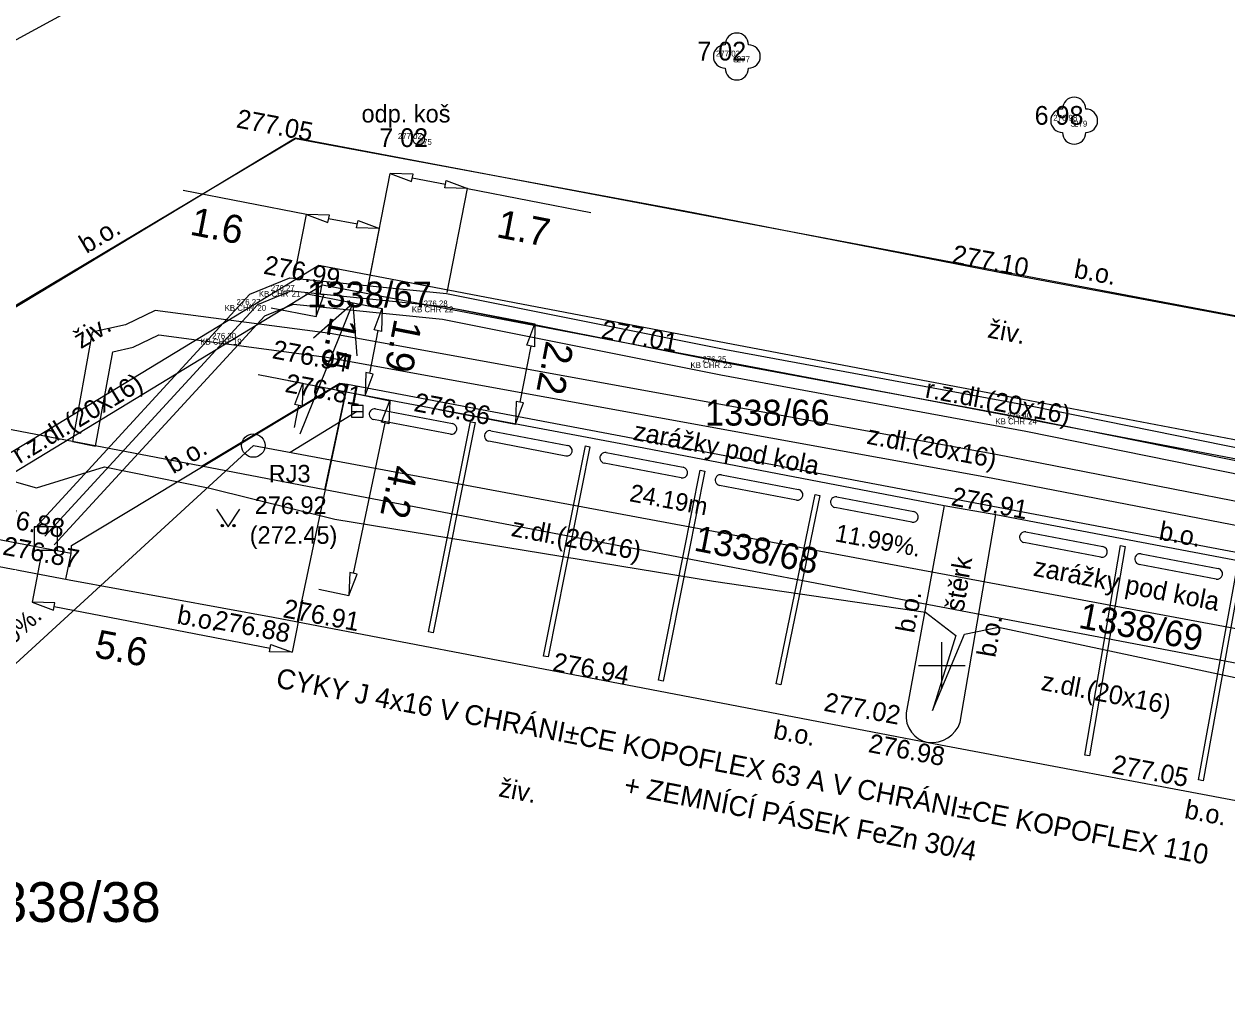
# Model space of a CAD drawing. Extents: x -601602 to -600882, y -1162594 to -1161950.
# Drawn here: x -601269.56 to -601243.92, y -1162082.3 to -1162061.32 of the extents above; entities that cross this region are included whole.
import ezdxf

# ---------------------------------------------------------------- set-up
doc = ezdxf.new("R2010")
doc.units = 0
for name, color, linetype in [('BODY', 7, 'Continuous'), ('BODY_CISLA', 7, 'Continuous'), ('BODY_KODY', 7, 'Continuous'), ('BODY_VYSKY_CELE', 7, 'Continuous'), ('G_TEXTY', 7, 'Continuous'), ('G_ZELEN', 7, 'Continuous'), ('G_ZNACKY', 7, 'Continuous'), ('H_KOTY_VYSKOVE', 7, 'Continuous'), ('H_VYSKY_PREVZATE', 7, 'Continuous'), ('IS_CHRÁNIČKY', 7, 'Continuous'), ('IS_KAN_JEDNOTNA', 7, 'Continuous'), ('IS_ODVODNĚNÍ', 7, 'Continuous'), ('IS_VO_PRELOZKA', 7, 'Continuous'), ('KN_Hranice parcel', 7, 'Continuous'), ('KN_Parcelní čísla', 7, 'Continuous'), ('KN_Pop  PČ popisy', 7, 'Continuous'), ('KN_Věcná břemena k části', 7, 'Continuous'), ('Vrstva 14', 7, 'Continuous'), ('Vrstva 23', 7, 'Continuous'), ('Vrstva 25', 7, 'Continuous'), ('VRSTVA 40', 7, 'Continuous'), ('Vrstva 49', 7, 'Continuous'), ('VRSTVA 5', 7, 'Continuous'), ('Vrstva 7', 7, 'Continuous'), ('X_SOUR_KRIZKY_SEVER', 7, 'Continuous')]:
    doc.layers.add(name, color=color, linetype=linetype)

# ---------------------------------------------------------------- blocks, each defined once
blk = doc.blocks.new('POINT_DISPLAY')
blk.add_line((0, 0), (0, 0))
blk = doc.blocks.new('1029_88')
at = {"layer": 'KN_Pop  PČ popisy'}
for p, q in [((0, 0), (1.124, 2.782)), ((1.124, 2.782), (0.285, 2.042)), ((1.124, 2.782), (1.213, 1.666))]:
    blk.add_line(p, q, dxfattribs=at)

msp = doc.modelspace()

# ---------------------------------------------------------------- linework, layer by layer
at = {"layer": 'G_ZELEN'}
for centre in [(-601254.37, -1162062.01), (-601247.18, -1162063.38)]:
    msp.add_circle(centre, 0.00025, dxfattribs=at)
for centre, start, end in [((-601254.37, -1162061.76), 0, 180), ((-601254.62, -1162062.01), 90, 270), ((-601254.12, -1162062.01), 270, 90), ((-601254.37, -1162062.26), 180, 360), ((-601247.18, -1162063.13), 0, 180), ((-601247.43, -1162063.38), 90, 270), ((-601246.93, -1162063.38), 270, 90), ((-601247.18, -1162063.63), 180, 360)]:
    msp.add_arc(centre, 0.25, start, end, dxfattribs=at)
at = {"layer": 'G_ZNACKY'}
for centre, radius in [((-601261.15, -1162063.77), 0.125), ((-601261.15, -1162063.77), 0.00025), ((-601264.676, -1162070.309), 0.25)]:
    msp.add_circle(centre, radius, dxfattribs=at)
at = {"layer": 'IS_CHRÁNIČKY'}
for points in [[(-601269.322, -1162072.054), (-601264.751, -1162067.079), (-601263.901, -1162066.729), (-601260.559, -1162067.068), (-601254.608, -1162068.26), (-601248.108, -1162069.46), (-601239.768, -1162071.15), (-601235.321, -1162071.969), (-601188.223, -1162080.219), (-601187.191, -1162077.25), (-601187.253, -1162076.744)], [(-601268.918, -1162072.426), (-601264.429, -1162067.541), (-601263.819, -1162067.291), (-601260.641, -1162067.612), (-601254.712, -1162068.8), (-601248.212, -1162070), (-601239.872, -1162071.69), (-601235.419, -1162072.511), (-601187.857, -1162080.841), (-601186.629, -1162077.31), (-601186.707, -1162076.676)]]:
    msp.add_lwpolyline(points, dxfattribs=at)
at = {"layer": 'IS_KAN_JEDNOTNA'}
msp.add_lwpolyline([(-601284.233, -1162104.983), (-601281.181, -1162099.025), (-601277.302, -1162081.896), (-601264.676, -1162070.309), (-601240.903, -1162074.739), (-601224.554, -1162077.728), (-601180.153, -1162087.436), (-601164.522, -1162091.613), (-601134.295, -1162101.261)], dxfattribs=at)
at = {"layer": 'IS_ODVODNĚNÍ'}
msp.add_line((-601262.46, -1162069.58), (-601263.89, -1162070.456), dxfattribs=at)
at = {"layer": 'IS_VO_PRELOZKA'}
msp.add_lwpolyline([(-601277.25, -1162070.85), (-601276.92, -1162070.27), (-601276.21, -1162070.04), (-601270.43, -1162070.89), (-601269.3, -1162071.21), (-601267.85, -1162070.76), (-601267.85, -1162070.76), (-601265.6, -1162071.22), (-601262.94, -1162071.88), (-601254.87, -1162073.2), (-601250.35, -1162073.86), (-601249.7, -1162074.36), (-601250.2, -1162075.96), (-601249.52, -1162074.33), (-601248.79, -1162074.18), (-601240.94, -1162075.85), (-601238.61, -1162076.29), (-601226.51, -1162078.06), (-601223.39, -1162080.54), (-601226.51, -1162078.06), (-601238.61, -1162076.29), (-601238.61, -1162076.29)], dxfattribs=at)
at = {"layer": 'KN_Hranice parcel'}
for p, q in [((-601263.15, -1162071.25), (-601262.67, -1162069)), ((-601262.67, -1162069), (-601240.88, -1162073.12)), ((-601265.78, -1162070.75), (-601273.06, -1162069.36)), ((-601263.15, -1162071.25), (-601265.78, -1162070.75))]:
    msp.add_line(p, q, dxfattribs=at)
for points in [[(-601238.38, -1162068.56), (-601263.78, -1162063.75), (-601273.06, -1162069.36)], [(-601265.78, -1162070.75), (-601262.83, -1162068.98), (-601262.67, -1162069)], [(-601241.2, -1162074.96), (-601241.86, -1162075.07), (-601242.73, -1162075.09), (-601243.52, -1162074.99), (-601263.15, -1162071.25)]]:
    msp.add_lwpolyline(points, dxfattribs=at)
at = {"layer": 'KN_Věcná břemena k části'}
msp.add_lwpolyline([(-601239.85, -1162072.76), (-601239.69, -1162072.29), (-601248.85, -1162070.5), (-601263.04, -1162067.92), (-601266.77, -1162067.43), (-601267.4, -1162067.73), (-601268.11, -1162067.89), (-601268.53, -1162070.22), (-601268.04, -1162070.32), (-601267.67, -1162068.31), (-601267.24, -1162068.21), (-601266.69, -1162067.95), (-601263.12, -1162068.42), (-601248.95, -1162071)], close=True, dxfattribs=at)
at = {"layer": 'Vrstva 14'}
for p, q in [((-601265.463, -1162071.667), (-601265.213, -1162072.042)), ((-601265.213, -1162072.042), (-601264.963, -1162071.667))]:
    msp.add_line(p, q, dxfattribs=at)
for points in [[(-601265.338, -1162072.042), (-601265.363, -1162072.017), (-601265.338, -1162071.992)], [(-601265.338, -1162072.042), (-601265.338, -1162071.992), (-601265.313, -1162072.017)], [(-601265.088, -1162072.042), (-601265.113, -1162072.017), (-601265.088, -1162071.992)], [(-601265.088, -1162072.042), (-601265.088, -1162071.992), (-601265.063, -1162072.017)]]:
    msp.add_lwpolyline(points, close=True, dxfattribs=at)
for centre in [(-601265.338, -1162072.017), (-601265.088, -1162072.017)]:
    msp.add_circle(centre, 0.025, dxfattribs=at)
at = {"layer": 'Vrstva 23'}
for p, q in [((-601268.85, -1162072.04), (-601269.35, -1162072.04)), ((-601269.35, -1162072.04), (-601269.35, -1162072.54)), ((-601268.85, -1162072.54), (-601268.85, -1162072.04)), ((-601269.35, -1162072.54), (-601268.85, -1162072.54))]:
    msp.add_line(p, q, dxfattribs=at)
at = {"layer": 'Vrstva 25'}
for p, q in [((-601262.335, -1162069.455), (-601262.585, -1162069.455)), ((-601262.585, -1162069.455), (-601262.585, -1162069.706)), ((-601262.585, -1162069.58), (-601262.335, -1162069.58)), ((-601262.335, -1162069.706), (-601262.335, -1162069.455)), ((-601262.585, -1162069.706), (-601262.335, -1162069.706)), ((-601262.585, -1162069.706), (-601262.585, -1162069.706))]:
    msp.add_line(p, q, dxfattribs=at)
at = {"layer": 'VRSTVA 40'}
for p, q in [((-601262.191, -1162066.724), (-601261.759, -1162064.507)), ((-601261.287, -1162064.598), (-601260.582, -1162064.736)), ((-601263.542, -1162065.378), (-601266.172, -1162064.865)), ((-601260.543, -1162067.046), (-601260.111, -1162064.828)), ((-601260.111, -1162064.828), (-601257.48, -1162065.34)), ((-601263.803, -1162066.716), (-601263.542, -1162065.378)), ((-601262.458, -1162065.589), (-601263.071, -1162065.469)), ((-601262.248, -1162067.018), (-601261.987, -1162065.68)), ((-601263.248, -1162067.083), (-601263.156, -1162066.612)), ((-601263.566, -1162067.067), (-601261.932, -1162067.386)), ((-601264.296, -1162067.368), (-601263.34, -1162067.554)), ((-601260.305, -1162067.397), (-601258.673, -1162067.714)), ((-601262.024, -1162067.857), (-601262.202, -1162068.768)), ((-601258.764, -1162068.185), (-601258.996, -1162069.381)), ((-601264.574, -1162068.792), (-601263.619, -1162068.979)), ((-601263.927, -1162068.921), (-601262.293, -1162069.239)), ((-601262.406, -1162069.222), (-601261.769, -1162069.356)), ((-601263.711, -1162069.45), (-601263.803, -1162069.921)), ((-601260.72, -1162069.536), (-601259.088, -1162069.852)), ((-601262.544, -1162073.035), (-601261.868, -1162069.826)), ((-601269.177, -1162072.535), (-601269.392, -1162073.65)), ((-601263.28, -1162073.37), (-601262.643, -1162073.504)), ((-601268.92, -1162073.741), (-601264.317, -1162074.627)), ((-601263.631, -1162073.603), (-601263.845, -1162074.718))]:
    msp.add_line(p, q, dxfattribs=at)
for points in [[(-601261.303, -1162064.677), (-601261.272, -1162064.52), (-601261.759, -1162064.507)], [(-601260.597, -1162064.814), (-601260.566, -1162064.657), (-601260.111, -1162064.828)], [(-601263.086, -1162065.548), (-601263.056, -1162065.391), (-601263.542, -1162065.378)], [(-601262.474, -1162065.667), (-601262.443, -1162065.51), (-601261.987, -1162065.68)], [(-601263.17, -1162067.099), (-601263.327, -1162067.068), (-601263.34, -1162067.554)], [(-601261.946, -1162067.872), (-601262.103, -1162067.841), (-601261.932, -1162067.386)], [(-601258.686, -1162068.2), (-601258.843, -1162068.17), (-601258.673, -1162067.714)], [(-601262.123, -1162068.783), (-601262.28, -1162068.753), (-601262.293, -1162069.239)], [(-601263.633, -1162069.465), (-601263.79, -1162069.435), (-601263.619, -1162068.979)], [(-601261.79, -1162069.842), (-601261.946, -1162069.809), (-601261.769, -1162069.356)], [(-601258.918, -1162069.396), (-601259.075, -1162069.366), (-601259.088, -1162069.852)], [(-601262.466, -1162073.051), (-601262.622, -1162073.018), (-601262.643, -1162073.504)], [(-601268.935, -1162073.819), (-601268.905, -1162073.662), (-601269.392, -1162073.65)], [(-601264.332, -1162074.706), (-601264.302, -1162074.549), (-601263.845, -1162074.718)]]:
    msp.add_lwpolyline(points, close=True, dxfattribs=at)
at = {"layer": 'VRSTVA 5'}
for p, q in [((-601263.86, -1162067.01), (-601264.59, -1162067.31)), ((-601263.86, -1162067.01), (-601260.6, -1162067.34)), ((-601264.59, -1162067.31), (-601269.12, -1162072.24)), ((-601260.6, -1162067.34), (-601254.66, -1162068.53)), ((-601254.66, -1162068.53), (-601248.16, -1162069.73)), ((-601248.16, -1162069.73), (-601239.82, -1162071.42))]:
    msp.add_line(p, q, dxfattribs=at)
at = {"layer": 'Vrstva 7'}
for p, q in [((-601273.54, -1162063.74), (-601268.18, -1162060.8)), ((-601273.03, -1162069.28), (-601263.78, -1162063.76)), ((-601263.78, -1162063.76), (-601255.48, -1162065.3)), ((-601255.48, -1162065.3), (-601248.56, -1162066.65)), ((-601270.7, -1162070.97), (-601263.28, -1162066.46)), ((-601263.28, -1162066.46), (-601256.02, -1162067.85)), ((-601248.56, -1162066.65), (-601239.96, -1162068.26)), ((-601270.34, -1162071.22), (-601263.2, -1162066.88)), ((-601263.2, -1162066.88), (-601256.09, -1162068.24)), ((-601256.02, -1162067.85), (-601249.02, -1162069.18)), ((-601256.09, -1162068.24), (-601249.09, -1162069.57)), ((-601268.55, -1162072.44), (-601262.83, -1162068.99)), ((-601262.83, -1162068.99), (-601262.66, -1162069.01)), ((-601262.66, -1162069.01), (-601262.7, -1162069.16)), ((-601263.734, -1162074.069), (-601262.7, -1162069.16)), ((-601262.7, -1162069.16), (-601256.35, -1162070.36)), ((-601249.02, -1162069.18), (-601240.39, -1162070.82)), ((-601262.07, -1162069.527), (-601260.43, -1162069.841)), ((-601249.09, -1162069.57), (-601240.46, -1162071.21)), ((-601260.473, -1162070.067), (-601262.113, -1162069.753)), ((-601259.614, -1162069.992), (-601257.974, -1162070.306)), ((-601258.017, -1162070.531), (-601259.657, -1162070.217)), ((-601256.35, -1162070.36), (-601249.95, -1162071.59)), ((-601255.557, -1162070.998), (-601257.197, -1162070.684)), ((-601257.154, -1162070.458), (-601255.514, -1162070.772)), ((-601254.695, -1162070.931), (-601253.055, -1162071.245)), ((-601253.098, -1162071.471), (-601254.739, -1162071.157)), ((-601252.237, -1162071.403), (-601250.596, -1162071.717)), ((-601250.64, -1162071.943), (-601252.28, -1162071.629)), ((-601249.95, -1162071.59), (-601250.76, -1162076.01)), ((-601249.95, -1162071.59), (-601248.85, -1162071.78)), ((-601249.61, -1162076.21), (-601248.85, -1162071.78)), ((-601248.85, -1162071.78), (-601240.89, -1162073.29)), ((-601273.96, -1162072.15), (-601268.6, -1162073.17)), ((-601248.208, -1162072.15), (-601246.568, -1162072.464)), ((-601268.56, -1162072.61), (-601270.53, -1162072.24)), ((-601268.56, -1162072.61), (-601268.55, -1162072.44)), ((-601246.611, -1162072.69), (-601248.251, -1162072.376)), ((-601268.675, -1162073.156), (-601268.56, -1162072.61)), ((-601245.752, -1162072.616), (-601244.112, -1162072.93)), ((-601244.155, -1162073.156), (-601245.795, -1162072.842)), ((-601268.6, -1162073.17), (-601264.25, -1162073.97)), ((-601264.25, -1162073.97), (-601257.04, -1162075.35)), ((-601257.04, -1162075.35), (-601250.29, -1162076.64)), ((-601250.29, -1162076.64), (-601241.98, -1162078.21))]:
    msp.add_line(p, q, dxfattribs=at)
for points in [[(-601260.939, -1162074.28), (-601260.049, -1162069.8), (-601259.951, -1162069.82), (-601260.841, -1162074.3)], [(-601258.489, -1162074.797), (-601257.599, -1162070.317), (-601257.501, -1162070.336), (-601258.391, -1162074.816)], [(-601256.039, -1162075.314), (-601255.149, -1162070.834), (-601255.051, -1162070.853), (-601255.941, -1162075.333)], [(-601252.601, -1162071.37), (-601253.431, -1162075.41), (-601253.529, -1162075.39), (-601252.699, -1162071.35)], [(-601246.949, -1162076.912), (-601246.189, -1162072.442), (-601246.091, -1162072.458), (-601246.851, -1162076.928)], [(-601243.611, -1162072.929), (-601244.431, -1162077.459), (-601244.529, -1162077.441), (-601243.709, -1162072.911)]]:
    msp.add_lwpolyline(points, close=True, dxfattribs=at)
for centre, radius, start, end in [((-601262.092, -1162069.64), 0.115, 79.1646, 259.1646), ((-601260.452, -1162069.954), 0.115, 259.1646, 79.1646), ((-601259.635, -1162070.105), 0.115, 79.1646, 259.1646), ((-601257.995, -1162070.418), 0.115, 259.1646, 79.1646), ((-601257.176, -1162070.571), 0.115, 79.1646, 259.1646), ((-601255.535, -1162070.885), 0.115, 259.1646, 79.1646), ((-601254.717, -1162071.044), 0.115, 79.1646, 259.1646), ((-601253.077, -1162071.358), 0.115, 259.1646, 79.1646), ((-601252.258, -1162071.516), 0.115, 79.1646, 259.1646), ((-601250.618, -1162071.83), 0.115, 259.1646, 79.1646), ((-601248.23, -1162072.263), 0.115, 79.1646, 259.1646), ((-601246.589, -1162072.577), 0.115, 259.1646, 79.1646), ((-601245.773, -1162072.729), 0.115, 79.1646, 259.1646), ((-601244.133, -1162073.043), 0.115, 259.1646, 79.1646), ((-601250.191, -1162076.076), 0.573, 173.3893, 260.0589), ((-601250.214, -1162076.007), 0.637, 263.1598, 341.4548)]:
    msp.add_arc(centre, radius, start, end, dxfattribs=at)
at = {"layer": 'X_SOUR_KRIZKY_SEVER'}
for p, q in [((-601250, -1162075.5), (-601250, -1162074.5)), ((-601250.5, -1162075), (-601249.5, -1162075))]:
    msp.add_line(p, q, dxfattribs=at)

# ---------------------------------------------------------------- block references
at = {"layer": 'BODY'}
for p in [(-601254.37, -1162062.01), (-601247.18, -1162063.38), (-601261.15, -1162063.77), (-601263.86, -1162067.01), (-601264.59, -1162067.31), (-601260.6, -1162067.34), (-601265.11, -1162068.03), (-601254.66, -1162068.53), (-601248.16, -1162069.73)]:
    msp.add_blockref('POINT_DISPLAY', p, dxfattribs=at)
at = {"layer": 'KN_Pop  PČ popisy'}
msp.add_blockref('1029_88', (-601263.68, -1162070.06), dxfattribs=at)

# ---------------------------------------------------------------- texts
at = {"layer": 'BODY_CISLA'}
for s, p in [('277', (-601254.37, -1162062.135)), ('279', (-601247.18, -1162063.505)), ('275', (-601261.15, -1162063.895)), ('21', (-601263.86, -1162067.135)), ('20', (-601264.59, -1162067.435)), ('22', (-601260.6, -1162067.465)), ('19', (-601265.11, -1162068.155)), ('23', (-601254.66, -1162068.655)), ('24', (-601248.16, -1162069.855))]:
    msp.add_text(s, height=0.125, dxfattribs=at).set_placement(p)
at = {"layer": 'BODY_KODY'}
for s, p in [('S', (-601254.451, -1162062.135)), ('S', (-601247.261, -1162063.505)), ('KB CHR', (-601264.558, -1162067.135)), ('KB CHR', (-601265.288, -1162067.435)), ('KB CHR', (-601261.298, -1162067.465)), ('KB CHR', (-601265.808, -1162068.155)), ('KB CHR', (-601255.358, -1162068.655)), ('KB CHR', (-601248.858, -1162069.855))]:
    msp.add_text(s, height=0.125, dxfattribs=at).set_placement(p)
at = {"layer": 'BODY_VYSKY_CELE'}
for s, p in [('277.02 ', (-601254.815, -1162062.01)), ('276.98 ', (-601247.625, -1162063.38)), ('277.02 ', (-601261.595, -1162063.77)), ('276.27 ', (-601264.305, -1162067.01)), ('276.27 ', (-601265.035, -1162067.31)), ('276.28 ', (-601261.045, -1162067.34)), ('276.30 ', (-601265.555, -1162068.03)), ('276.35 ', (-601255.105, -1162068.53)), ('276.40 ', (-601248.605, -1162069.73))]:
    msp.add_text(s, height=0.125, dxfattribs=at).set_placement(p)
at = {"layer": 'G_TEXTY'}
msp.add_text('odp. koš', height=0.375, dxfattribs=at).set_placement((-601262.37, -1162063.417))
at = {"layer": 'H_KOTY_VYSKOVE'}
for s, p in [(' 7 02', (-601255.361, -1162062.096)), (' 6 98', (-601248.171, -1162063.466)), (' 7 02', (-601262.141, -1162063.941))]:
    msp.add_text(s, height=0.4, dxfattribs=at).set_placement(p)
at = {"layer": 'H_VYSKY_PREVZATE'}
for s, p in [('277.05 ', (-601265.057, -1162063.52)), ('277.10 ', (-601249.802, -1162066.416)), ('276.99 ', (-601264.477, -1162066.64)), ('277.01 ', (-601257.282, -1162068.016)), ('276.94 ', (-601264.292, -1162068.444)), ('276.81 ', (-601264.02, -1162069.162)), ('276.86 ', (-601261.273, -1162069.57)), ('276.91 ', (-601249.82, -1162071.58)), ('276.88 ', (-601270.352, -1162071.976)), ('276.87 ', (-601270.039, -1162072.631)), ('276.91 ', (-601264.063, -1162073.968)), ('276.88 ', (-601265.544, -1162074.211)), ('276.94 ', (-601258.317, -1162075.11)), ('277.02 ', (-601252.535, -1162075.962)), ('276.98 ', (-601251.587, -1162076.843)), ('277.05 ', (-601246.397, -1162077.291))]:
    msp.add_text(s, height=0.4, rotation=349.3397, dxfattribs=at).set_placement(p)
at = {"layer": 'IS_KAN_JEDNOTNA'}
for s, p in [('RJ3', (-601264.348, -1162071.095)), ('276.92', (-601264.647, -1162071.769)), ('(272.45)', (-601264.753, -1162072.404))]:
    msp.add_text(s, height=0.375, dxfattribs=at).set_placement(p)
for s, rotation, p in [('24.19m', 349.4442, (-601256.675, -1162071.493)), ('11.99%.', 349.4442, (-601252.295, -1162072.347)), ('11.09%.', 42.5429, (-601270.509, -1162075.221))]:
    msp.add_text(s, height=0.375, rotation=rotation, dxfattribs=at).set_placement(p)
at = {"layer": 'IS_VO_PRELOZKA'}
for s, p in [('CYKY J 4x16 V CHRÁNI±CE KOPOFLEX 63 A V CHRÁNI±CE KOPOFLEX 110', (-601264.214, -1162075.464)), ('+ ZEMNÍCÍ PÁSEK FeZn 30/4', (-601256.799, -1162077.743))]:
    msp.add_text(s, height=0.425, rotation=349.2056, dxfattribs=at).set_placement(p)
at = {"layer": 'KN_Parcelní čísla'}
for s, height, p in [('1338/67', 0.55, (-601263.529, -1162067.36)), ('1338/66', 0.55, (-601255.051, -1162069.882)), ('1338/38', 0.85, (-601270.76, -1162080.47))]:
    msp.add_text(s, height=height, dxfattribs=at).set_placement(p)
for s, p in [('1338/68', (-601255.304, -1162072.544)), ('1338/69', (-601247.108, -1162074.192))]:
    msp.add_text(s, height=0.55, rotation=349, dxfattribs=at).set_placement(p)
at = {"layer": 'VRSTVA 40'}
for s, rotation, p in [('1.6', 348.975, (-601266.05, -1162065.806)), ('1.7', 348.975, (-601259.517, -1162065.86)), ('1.5', 258.9342, (-601263.032, -1162067.539)), ('1.9', 258.975, (-601261.665, -1162067.584)), ('2.2', 259.0181, (-601258.433, -1162068.055)), ('4.2', 258.1026, (-601261.744, -1162070.695)), ('5.6', 349.0993, (-601268.088, -1162074.818))]:
    msp.add_text(s, height=0.6, rotation=rotation, dxfattribs=at).set_placement(p)
at = {"layer": 'Vrstva 49'}
for s, rotation, p in [('b.o.', 30.8269, (-601268.234, -1162066.225)), ('b.o.', 349.3964, (-601247.202, -1162066.723)), ('živ.', 349.242, (-601249.045, -1162067.999)), ('živ.', 31.2919, (-601268.352, -1162068.256)), ('r.z.dl.(20x16)', 31.293, (-601269.66, -1162070.706)), ('r.z.dl.(20x16)', 349.242, (-601250.373, -1162069.279)), ('zarážky pod kola', 349.1211, (-601256.599, -1162070.183)), ('z.dl.(20x16)', 349.1211, (-601251.621, -1162070.265)), ('b.o.', 31.0961, (-601266.384, -1162070.924)), ('b.o.', 349.2255, (-601266.323, -1162074.1))]:
    msp.add_text(s, height=0.4, rotation=rotation, dxfattribs=at).set_placement(p)
at = {"layer": 'Vrstva 7'}
for s, rotation, p in [('z.dl.(20x16)', 349.1211, (-601259.197, -1162072.234)), ('b.o.', 349.2587, (-601245.393, -1162072.31)), ('štěrk', 80.6666, (-601249.539, -1162073.859)), ('zarážky pod kola', 349.1211, (-601248.07, -1162073.08)), ('b.o.', 79.6153, (-601250.593, -1162074.324)), ('b.o.', 80.2652, (-601248.862, -1162074.843)), ('z.dl.(20x16)', 349.1211, (-601247.904, -1162075.518)), ('b.o.', 349.2255, (-601253.61, -1162076.553)), ('živ.', 349.1646, (-601259.466, -1162077.787)), ('b.o.', 349.2255, (-601244.847, -1162078.251))]:
    msp.add_text(s, height=0.4, rotation=rotation, dxfattribs=at).set_placement(p)

doc.saveas('drawing.dxf')
